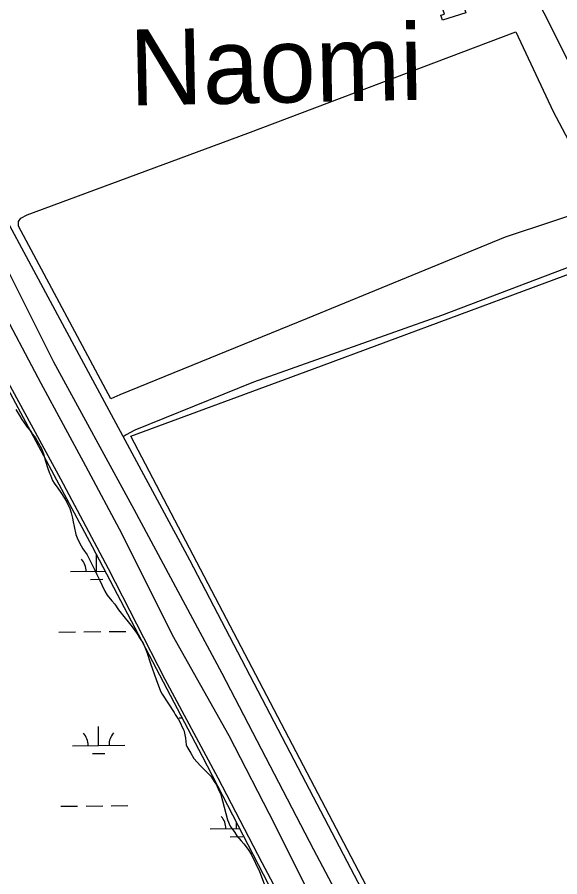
# Model space of a CAD drawing. Extents: x 3684037 to 3722149, y 433263 to 459021.
# Drawn here: x 3705639 to 3706676, y 440462 to 442103 of the extents above; entities that cross this region are included whole.
import ezdxf

# ---------------------------------------------------------------- set-up
doc = ezdxf.new("R2010")
doc.units = 0
for name, color, linetype in [('V-BLDG-OTLN', 7, 'Continuous'), ('V-LEVE-TOET', 7, 'Continuous'), ('V-RIVR-EDGE', 7, 'Continuous'), ('V-ROAD-CNTR', 7, 'Continuous'), ('V-SITE-VEGE', 7, 'Continuous'), ('V-TOPO-GNAM-IDEN', 7, 'Continuous'), ('V-TOPO-SHOR', 7, 'Continuous'), ('V-WETL-SWMP', 7, 'Continuous')]:
    doc.layers.add(name, color=color, linetype=linetype)

msp = doc.modelspace()

# ---------------------------------------------------------------- linework, layer by layer
at = {"layer": 'V-BLDG-OTLN'}
msp.add_lwpolyline([(3706447.4, 442132.6), (3706485, 442145), (3706495.9, 442112.1), (3706451.7, 442097.5), (3706448.5, 442107.2), (3706455.1, 442109.4)], close=True, dxfattribs=at)
at = {"layer": 'V-LEVE-TOET'}
for points in [[(3706288.8, 440144.2), (3706204.8, 440303.5), (3706106.8, 440488.5), (3706022.8, 440650.2), (3705921.9, 440838.7), (3705813.6, 441049.9), (3705722.6, 441221.2), (3705614.1, 441420.5), (3705507.4, 441618), (3705410.6, 441798.8), (3705323.5, 441958.7), (3705256.9, 442085.8), (3705182.5, 442211.2)], [(3705258.8, 442196.2), (3705352.2, 442030.9), (3705430.5, 441887.7), (3705522.1, 441715.8), (3705599.7, 441562.5), (3705683.8, 441404.4), (3705769.7, 441246.8), (3705838.6, 441116.8), (3705935.3, 440924.1), (3706043.3, 440731.3), (3706130.8, 440562.5), (3706220.5, 440381.8), (3706285, 440271.3), (3706336.4, 440179.6)]]:
    msp.add_lwpolyline(points, dxfattribs=at)
at = {"layer": 'V-RIVR-EDGE'}
msp.add_spline([(3705459.3, 448025.4), (3705478.2, 447991), (3705490.6, 447962.7), (3705497.9, 447946.9), (3705515.2, 447915.3), (3705550.2, 447853.8), (3705577.2, 447806.4), (3705592.1, 447777.2), (3705613, 447735.5), (3705627.1, 447702.7), (3705648.4, 447660.6), (3705670.9, 447613.3), (3705688.6, 447575.6), (3705703.1, 447542.8), (3705728.1, 447487.8), (3705750.2, 447433.1), (3705764.2, 447399.5), (3705787.6, 447350.5), (3705800.4, 447321.8), (3705823.8, 447277.7), (3705853.1, 447212.9), (3705867.2, 447179.7), (3705884.5, 447148.5), (3705906.2, 447095.5), (3705936, 447039.6), (3705952.5, 446996.3), (3705954.5, 446986.6), (3705964.5, 446959.1), (3705978.2, 446928.3), (3706001.9, 446883.8), (3706017.2, 446850.2), (3706031.3, 446824.3), (3706060.3, 446774.8), (3706084.9, 446736.8), (3706095.8, 446723.4), (3706096.2, 446720.2), (3706091.3, 446714.5), (3706089.7, 446713.3), (3706090.5, 446708.9), (3706096.1, 446705.6), (3706103, 446703.6), (3706108.6, 446696.7), (3706116.3, 446683.3), (3706130, 446657), (3706163.4, 446591.8), (3706169.4, 446575.6), (3706187.1, 446537.6), (3706212.8, 446473.6), (3706230.1, 446432.3), (3706247.4, 446398.3), (3706265.1, 446371.2), (3706278.8, 446345.3), (3706293.7, 446309.7), (3706314.6, 446262.3), (3706333.5, 446225.8), (3706356, 446180.1), (3706380.2, 446133.5), (3706396.3, 446102.4), (3706412.8, 446074.8), (3706429.7, 446038.8), (3706447, 445997.9), (3706455.4, 445962.3), (3706478.2, 445886.2), (3706492.7, 445852.2), (3706510.4, 445809.7), (3706528.1, 445771.7), (3706558.3, 445705.3), (3706582.8, 445657.1), (3706597.7, 445624.3), (3706628.3, 445558.3), (3706659.6, 445483), (3706677.7, 445432.8), (3706697, 445381), (3706750.1, 445262.4), (3706782.6, 445193.2), (3706806.8, 445141.8), (3706827.7, 445093.6), (3706851, 445029.3), (3706864.2, 444984.3), (3706871.8, 444949.5), (3706889.5, 444896.9), (3706899.9, 444865.8), (3706912.4, 444832.2), (3706928.8, 444798.2), (3706942.5, 444773.5), (3706966.3, 444725.3), (3706990.4, 444679.5), (3707017, 444624.5), (3707033.9, 444586), (3707080.5, 444482), (3707095.4, 444444.7), (3707112.3, 444405.1), (3707123.1, 444381.2), (3707171.4, 444273.5), (3707203.2, 444200.6), (3707218, 444163.8), (3707250.2, 444096.2), (3707257.4, 444074.3), (3707269.9, 444041.6), (3707288.4, 443990.6), (3707304, 443950.1), (3707343, 443838), (3707365.9, 443772), (3707378.7, 443728.7), (3707379.9, 443714.1), (3707381.1, 443702.8), (3707387.5, 443682.2), (3707398.3, 443657.1), (3707418.1, 443619), (3707439, 443578.5), (3707454.3, 443542.1), (3707473.1, 443492.7), (3707483.2, 443464.4), (3707531.1, 443368), (3707542.7, 443345), (3707550.8, 443323.9), (3707556.8, 443302.5), (3707556.8, 443297.6), (3707558.8, 443289.1), (3707568.4, 443273.3), (3707583.7, 443244.6), (3707593.8, 443221.9), (3707598.2, 443213.4), (3707609.5, 443204.9), (3707611.9, 443195.2), (3707611.9, 443180.6), (3707615.5, 443168.1), (3707621.9, 443150.3), (3707634.4, 443126.8), (3707648.1, 443102.1), (3707655.3, 443081.8), (3707660.5, 443073.3), (3707674.2, 443051.5), (3707678.6, 443034.1), (3707682.6, 443015.5), (3707689.5, 442998.5), (3707701.9, 442964.5), (3707714, 442928.4), (3707721.2, 442903.3), (3707726.4, 442888.8), (3707738.1, 442871.8), (3707743.7, 442857.2), (3707744.5, 442845.1), (3707747.3, 442826.1), (3707753.7, 442815.5), (3707763, 442801.3), (3707770.2, 442783.9), (3707772.6, 442762.1), (3707776.2, 442738.2), (3707779.8, 442720), (3707786.6, 442702.6), (3707805.5, 442663.3), (3707822.8, 442627.3), (3707832, 442599.4), (3707839.2, 442573.9), (3707845.7, 442561.3), (3707852.5, 442552.4), (3707860.2, 442541.9), (3707869.5, 442530.6), (3707886.4, 442507.9), (3707898.9, 442479.9), (3707916.1, 442434.6), (3707928.6, 442395.8), (3707943.4, 442356.5), (3707965.6, 442316.4), (3707989.7, 442269), (3708009.8, 442227.7), (3708024.7, 442192.5), (3708061.3, 442114.4), (3708074.2, 442088.5), (3708094.3, 442045.6), (3708116, 441996.6), (3708126.1, 441968.3), (3708137.7, 441927.8), (3708147.3, 441899.5), (3708157.8, 441868.3), (3708179.1, 441812.4), (3708204, 441746.9), (3708227.7, 441693.8), (3708249.8, 441646.1), (3708265.1, 441615.3), (3708271.5, 441595.9), (3708278.4, 441582.1), (3708308.1, 441508.4), (3708330.6, 441457.8), (3708349.9, 441405.2), (3708369.6, 441340.1), (3708384, 441295.6), (3708395.3, 441268.4), (3708411.8, 441234.8), (3708423.4, 441209.3), (3708441.1, 441169.7), (3708458.4, 441135.2), (3708469.3, 441110.5), (3708475.3, 441089.1), (3708486.9, 441061.6), (3708507.1, 441017.4), (3708523.5, 440978.6), (3708539.2, 440935.7), (3708564.1, 440883.1), (3708587.1, 440841.3), (3708595.1, 440826.8), (3708600.4, 440809.4), (3708606.7, 440778.2), (3708615.6, 440755.1), (3708636.9, 440692), (3708652.9, 440644.3), (3708673.4, 440592), (3708688.7, 440554.4), (3708706, 440506.6), (3708725.7, 440462.9), (3708743.4, 440422.4), (3708759.4, 440387.6), (3708800.1, 440293.3), (3708821, 440246.3), (3708835, 440211.5), (3708849.1, 440180.4), (3708876.1, 440124.9), (3708892.2, 440093.7), (3708912.3, 440054.9), (3708922.3, 440031), (3708932, 439999.8), (3708939.2, 439978.8), (3708948, 439954.1), (3708952.4, 439931.8), (3708956, 439911.6), (3708960, 439899.5), (3708969.6, 439870.3), (3708986.9, 439829.8), (3708999.4, 439794.2), (3709014.7, 439755.4), (3709034.7, 439705.2), (3709046.8, 439671.6), (3709063.3, 439633.1), (3709075.8, 439614.5), (3709093.1, 439592.6), (3709106, 439574.4), (3709121.7, 439548.9), (3709151.5, 439484.1), (3709171.6, 439447.3), (3709197.4, 439407.6), (3709211.1, 439376.8), (3709222.3, 439350.1), (3709240.4, 439308.8), (3709252.9, 439281.7), (3709266.1, 439254.9), (3709271, 439245.6), (3709296.3, 439199.9), (3709313.2, 439159), (3709331.3, 439114.9), (3709341.3, 439082.5), (3709360.3, 439046.5), (3709378.8, 439008.8), (3709407.7, 438944.4), (3709416.4, 438923.6)], degree=3, dxfattribs=at)
at = {"layer": 'V-ROAD-CNTR'}
msp.add_lwpolyline([(3706450.1, 442499.9), (3706904.6, 441595.9), (3707446.7, 440515.3), (3707834.7, 439738.8), (3708246.6, 438913.6)], dxfattribs=at)
at = {"layer": 'V-SITE-VEGE'}
for p, q in [((3705636.2, 441354.3), (3705643.3, 441342.7)), ((3705643.3, 441342.7), (3705648, 441335.2)), ((3705648, 441335.2), (3705656.5, 441322.1)), ((3705656.5, 441322.1), (3705657.9, 441320.2)), ((3705657.9, 441320.2), (3705659.8, 441318.4)), ((3705659.8, 441318.4), (3705665.4, 441311.4)), ((3705665.4, 441311.4), (3705668.2, 441307.2)), ((3705668.2, 441307.2), (3705673.9, 441300.2)), ((3705673.9, 441300.2), (3705685.2, 441279.6)), ((3705685.2, 441279.6), (3705689, 441269.8)), ((3705689, 441269.8), (3705693.2, 441255.3)), ((3705693.2, 441255.3), (3705697, 441243.6)), ((3705697, 441243.6), (3705700.8, 441232.4)), ((3705700.8, 441232.4), (3705702.7, 441229.1)), ((3705702.7, 441229.1), (3705706.4, 441218.8)), ((3705706.4, 441218.8), (3705709.3, 441213.7)), ((3705709.3, 441213.7), (3705716.3, 441203.9)), ((3705716.3, 441203.9), (3705722, 441195.5)), ((3705722, 441195.5), (3705729, 441184.7)), ((3705729, 441184.7), (3705733.7, 441177.2)), ((3705733.7, 441177.2), (3705739.4, 441165.1)), ((3705739.4, 441165.1), (3705742.2, 441156.7)), ((3705742.2, 441156.7), (3705744.6, 441146.8)), ((3705744.6, 441146.8), (3705746, 441139.8)), ((3705746, 441139.8), (3705747.5, 441130.9)), ((3705747.5, 441130.9), (3705750.8, 441115.5)), ((3705750.8, 441115.5), (3705753.6, 441109.4)), ((3705753.6, 441109.4), (3705757.9, 441099.6)), ((3705757.9, 441099.6), (3705764.5, 441087.9)), ((3705764.5, 441087.9), (3705772.4, 441076.7)), ((3705772.4, 441076.7), (3705781.4, 441058.5)), ((3705781.4, 441058.5), (3705787.1, 441047.3)), ((3705787.1, 441047.3), (3705791.3, 441039.3)), ((3705791.3, 441039.3), (3705796.9, 441027.6)), ((3705796.9, 441027.6), (3705800.7, 441019.2)), ((3705800.7, 441019.2), (3705806.4, 441007.1)), ((3705806.4, 441007.1), (3705811.1, 440999.6)), ((3705811.1, 440999.6), (3705820, 440988.8)), ((3705820, 440988.8), (3705825.2, 440982.3)), ((3705825.2, 440982.3), (3705832.7, 440971.6)), ((3705832.7, 440971.6), (3705839.8, 440961.8)), ((3705839.8, 440961.8), (3705856.2, 440942.2)), ((3705856.2, 440942.2), (3705862.3, 440934.2)), ((3705862.3, 440934.2), (3705869.4, 440923.9)), ((3705869.4, 440923.9), (3705872.7, 440918.3)), ((3705872.7, 440918.3), (3705876.4, 440912.3)), ((3705876.4, 440912.3), (3705878.8, 440909)), ((3705878.8, 440909), (3705883, 440900.6)), ((3705883, 440900.6), (3705886.3, 440890.8)), ((3705886.3, 440890.8), (3705893.4, 440868.8)), ((3705893.4, 440868.8), (3705904.3, 440838.8)), ((3705904.3, 440838.8), (3705912.8, 440816.4)), ((3705912.8, 440816.4), (3705916.1, 440810.8)), ((3705916.1, 440810.8), (3705926.9, 440794)), ((3705926.9, 440794), (3705939.1, 440775.8)), ((3705939.1, 440775.8), (3705941, 440772)), ((3705941, 440772), (3705947.1, 440762.2)), ((3705947.1, 440762.2), (3705950.4, 440756.1)), ((3705950.4, 440756.1), (3705954.7, 440746.3)), ((3705954.7, 440746.3), (3705957, 440741.6)), ((3705957, 440741.6), (3705958, 440739.3)), ((3705958, 440739.3), (3705960.4, 440726.7)), ((3705960.4, 440726.7), (3705961.3, 440720.1)), ((3705961.3, 440720.1), (3705961.8, 440714)), ((3705961.8, 440714), (3705963.2, 440710.8)), ((3705963.2, 440710.8), (3705970.8, 440697.7)), ((3705970.8, 440697.7), (3705976.4, 440687.4)), ((3705976.4, 440687.4), (3705989.1, 440673.9)), ((3705989.1, 440673.9), (3706002.7, 440660.3)), ((3706002.7, 440660.3), (3706008.8, 440653.8)), ((3706008.8, 440653.8), (3706015.4, 440644)), ((3706015.4, 440644), (3706019.6, 440637.5)), ((3706019.6, 440637.5), (3706024.4, 440626.7)), ((3706024.4, 440626.7), (3706027.7, 440618.8)), ((3706027.7, 440618.8), (3706040.5, 440570.6)), ((3706040.5, 440570.6), (3706046.1, 440558.4)), ((3706046.1, 440558.4), (3706054.6, 440546.3)), ((3706054.6, 440546.3), (3706058.8, 440539.7)), ((3706058.8, 440539.7), (3706066.8, 440530.4)), ((3706066.8, 440530.4), (3706072, 440524.8)), ((3706072, 440524.8), (3706080.4, 440514.1)), ((3706080.4, 440514.1), (3706086.1, 440504.7)), ((3706086.1, 440504.7), (3706102.1, 440472)), ((3706102.1, 440472), (3706116.7, 440432.7))]:
    msp.add_line(p, q, dxfattribs=at)
msp.add_lwpolyline([(3705817.9, 441374.7), (3705641.5, 441704.4), (3705641.7, 441713.2), (3705645.8, 441719.5), (3705658.2, 441725.8), (3706079.7, 441881.7), (3706591.3, 442075.2), (3706663.1, 441923.5), (3706754.8, 441750.1), (3706752.4, 441743), (3706571.1, 441683.5), (3706192.8, 441527.7), (3705834.7, 441382.3)], close=True, dxfattribs=at)
msp.add_lwpolyline([(3706923.4, 440341.6), (3706626.4, 440229.8), (3706501.2, 440183.9), (3706488.3, 440180), (3706474.2, 440177.2), (3706462.5, 440176.8), (3706456.7, 440178.6), (3706442.7, 440184.6), (3706438.7, 440191.1), (3705856, 441303.3), (3706203.1, 441431), (3706766.2, 441640.3)], dxfattribs=at)
at = {"layer": 'V-TOPO-SHOR'}
for points in [[(3705292.3, 442220.9), (3705391.6, 442054.7), (3705530.1, 441800.2), (3705708.4, 441445.2), (3705861.9, 441163.6), (3706029.6, 440850.9), (3706205.2, 440514), (3706424.9, 440098.8), (3706534.3, 439905.5)], [(3705415.6, 442108.2), (3705523, 441892.8), (3705752, 441467.5), (3705968.4, 441066.9), (3706182.9, 440655.9), (3706432.9, 440177.7), (3706570.9, 439926.2)], [(3706758.5, 441650.6), (3706449.6, 441533.6), (3706090.5, 441406.4), (3705863.4, 441314.6), (3705847.1, 441306), (3705841.5, 441301.9)]]:
    msp.add_lwpolyline(points, dxfattribs=at)
at = {"layer": 'V-WETL-SWMP'}
for p, q in [((3705790.6, 441045.3), (3705790.2, 441077.7)), ((3705740.6, 441044.7), (3705807.2, 441045.5)), ((3705778.8, 441029.7), (3705802.8, 441030)), ((3705718.5, 440929), (3705750.5, 440929.4)), ((3705766.5, 440929.6), (3705798.5, 440929.9)), ((3705814.5, 440930.1), (3705846.5, 440930.5)), ((3705948.5, 440765.2), (3705954.2, 440765.2)), ((3705794.5, 440712.6), (3705794.1, 440748.6)), ((3705744.5, 440712.1), (3705844.5, 440713.2)), ((3705782.7, 440697.1), (3705806.6, 440697.3)), ((3705818.4, 440597.5), (3705850.4, 440597.9)), ((3705722.4, 440596.4), (3705754.4, 440596.7)), ((3705770.4, 440596.9), (3705802.4, 440597.3)), ((3706057.8, 440553.8), (3706057.6, 440566.2)), ((3706007.8, 440553.2), (3706064, 440553.9)), ((3706046, 440538.3), (3706070, 440538.5))]:
    msp.add_line(p, q, dxfattribs=at)
msp.add_lwpolyline([(3706710.8, 439280.3), (3706638.2, 439406.3), (3706595.5, 439502), (3706548, 439591.9), (3706505.3, 439687.6), (3706453, 439784.2), (3706398.7, 439890), (3706353.6, 439980.4), (3706304.2, 440068.4), (3706268.8, 440140.5), (3706235.4, 440222.1), (3705992.8, 440691.7), (3705782.7, 441092.1), (3705616.6, 441402.9), (3705394.6, 441810.6), (3705259.9, 442062.8), (3705038.5, 442412.3)], dxfattribs=at)
for centre, start, end in [((3705735.4, 441045.1), 359.8949, 41.4385), ((3705739.2, 440712.5), 359.8949, 41.4385), ((3705849.7, 440713.8), 139.8949, 181.4385), ((3706002.5, 440553.7), 359.8949, 41.4385)]:
    msp.add_arc(centre, 35.2, start, end, dxfattribs=at)

# ---------------------------------------------------------------- texts
at = {"layer": 'V-TOPO-GNAM-IDEN'}
msp.add_text('Naomi', height=145, rotation=1.1351, dxfattribs=at).set_placement((3705854.7, 441934.6))

doc.saveas('drawing.dxf')
